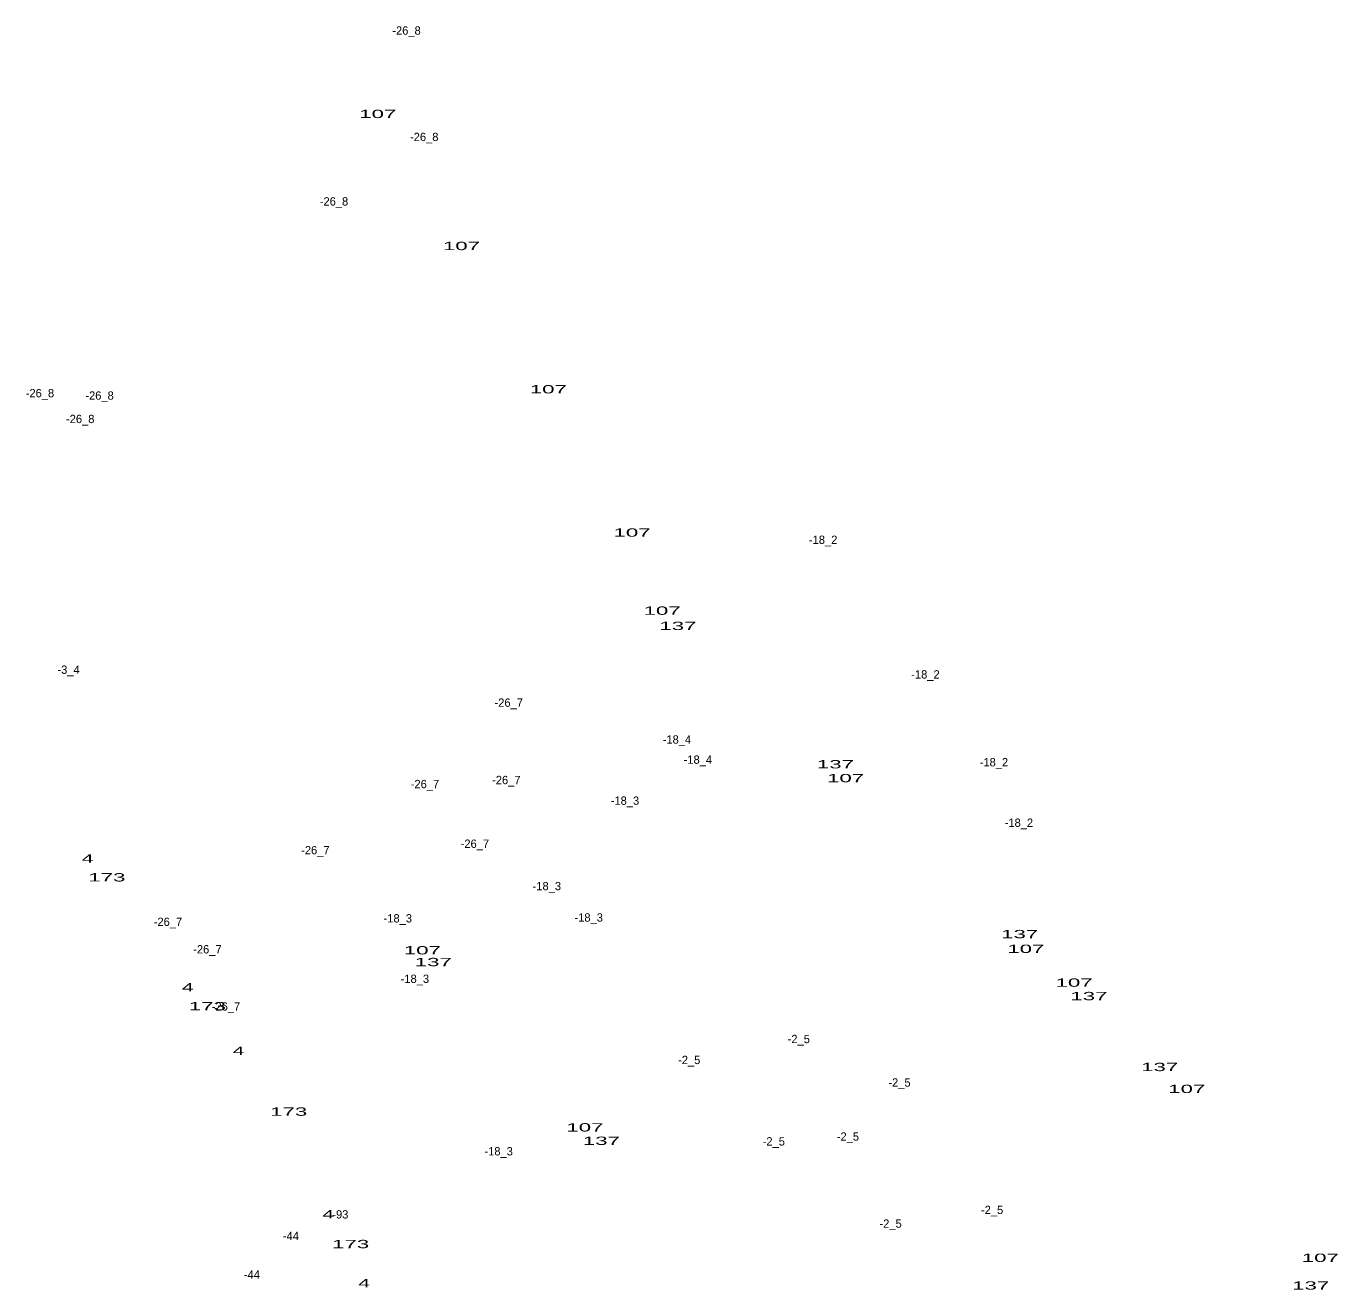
# Model space of a CAD drawing. Extents: x -656096 to -652763, y -1002270 to -998958.
# Drawn here: x -653525 to -652894, y -1001662 to -1001054 of the extents above; entities that cross this region are included whole.
import ezdxf
from ezdxf.enums import TextEntityAlignment as Align

# ---------------------------------------------------------------- set-up
doc = ezdxf.new("R2010")
doc.units = 0
doc.header["$LTSCALE"] = 1.6
doc.layers.add('24', color=7, linetype='Continuous')

msp = doc.modelspace()

# ---------------------------------------------------------------- texts
at = {"layer": '24'}
for s, p in [('-26_8', (-653342.078, -1001058.13)), ('-26_8', (-653333.548, -1001109.33)), ('-26_8', (-653376.978, -1001140.36)), ('-26_8', (-653518.498, -1001232.63)), ('-26_8', (-653489.808, -1001233.79)), ('-26_8', (-653499.118, -1001245.04)), ('-18_2', (-653141.556, -1001303.18)), ('-3_4', (-653504.728, -1001365.69)), ('-18_2', (-653092.316, -1001367.95)), ('-26_7', (-653292.884, -1001381.55)), ('-18_4', (-653211.93, -1001399.28)), ('-18_4', (-653201.85, -1001408.98)), ('-18_2', (-653059.356, -1001410.23)), ('-26_7', (-653333.204, -1001420.73)), ('-26_7', (-653294.044, -1001418.79)), ('-18_3', (-653236.936, -1001428.71)), ('-18_2', (-653047.336, -1001439.32)), ('-26_7', (-653385.944, -1001452.54)), ('-26_7', (-653309.174, -1001449.43)), ('-18_3', (-653274.546, -1001469.83)), ('-18_3', (-653254.386, -1001484.95)), ('-26_7', (-653456.894, -1001487.02)), ('-18_3', (-653346.276, -1001485.34)), ('-26_7', (-653437.894, -1001500.24)), ('-18_3', (-653338.056, -1001514.43)), ('-26_7', (-653428.984, -1001527.75)), ('-2_5', (-653153.283, -1001543.41)), ('-2_5', (-653206.013, -1001553.49)), ('-2_5', (-653104.823, -1001564.35)), ('-2_5', (-653129.633, -1001590.34)), ('-18_3', (-653297.736, -1001597.44)), ('-2_5', (-653165.303, -1001592.67)), ('-93', (-653373.93, -1001627.8)), ('-2_5', (-653060.233, -1001625.64)), ('-2_5', (-653109.083, -1001632.23)), ('-44', (-653397.703, -1001638.18)), ('-44', (-653416.493, -1001656.78))]:
    msp.add_text(s, height=4, dxfattribs=at).set_placement(p, align=Align.CENTER)
for s, width, p in [('107', 2, (-653355.909, -1001098.26)), ('107', 2, (-653315.629, -1001161.79)), ('107', 2, (-653273.809, -1001230.75)), ('107', 2, (-653233.529, -1001299.71)), ('107', 2, (-653219.049, -1001337.28)), ('137', 2, (-653211.473, -1001344.61)), ('137', 2, (-653135.643, -1001411.19)), ('107', 2, (-653130.749, -1001417.87)), ('4', 1.9, (-653495.547, -1001456.57)), ('173', 2, (-653486.293, -1001465.61)), ('137', 2, (-653046.963, -1001492.93)), ('107', 2, (-653334.449, -1001500.7)), ('107', 2, (-653043.999, -1001500)), ('137', 2, (-653329.203, -1001506.37)), ('107', 2, (-653020.769, -1001516.27)), ('4', 1.9, (-653447.337, -1001518.52)), ('137', 2, (-653013.663, -1001522.76)), ('173', 2, (-653437.893, -1001527.59)), ('4', 1.9, (-653422.907, -1001549.11)), ('137', 2, (-652979.583, -1001556.85)), ('107', 2, (-652966.549, -1001567.41)), ('173', 2, (-653398.773, -1001578.34)), ('107', 2, (-653256.219, -1001585.93)), ('137', 2, (-653248.263, -1001592.38)), ('4', 1.9, (-653379.727, -1001627.73)), ('173', 2, (-653368.953, -1001642.07)), ('107', 2, (-652902.259, -1001648.69)), ('4', 1.9, (-653362.477, -1001660.89)), ('137', 2, (-652906.893, -1001662.02))]:
    msp.add_text(s, height=4, dxfattribs=dict(at, width=width)).set_placement(p, align=Align.CENTER)

doc.saveas('drawing.dxf')
